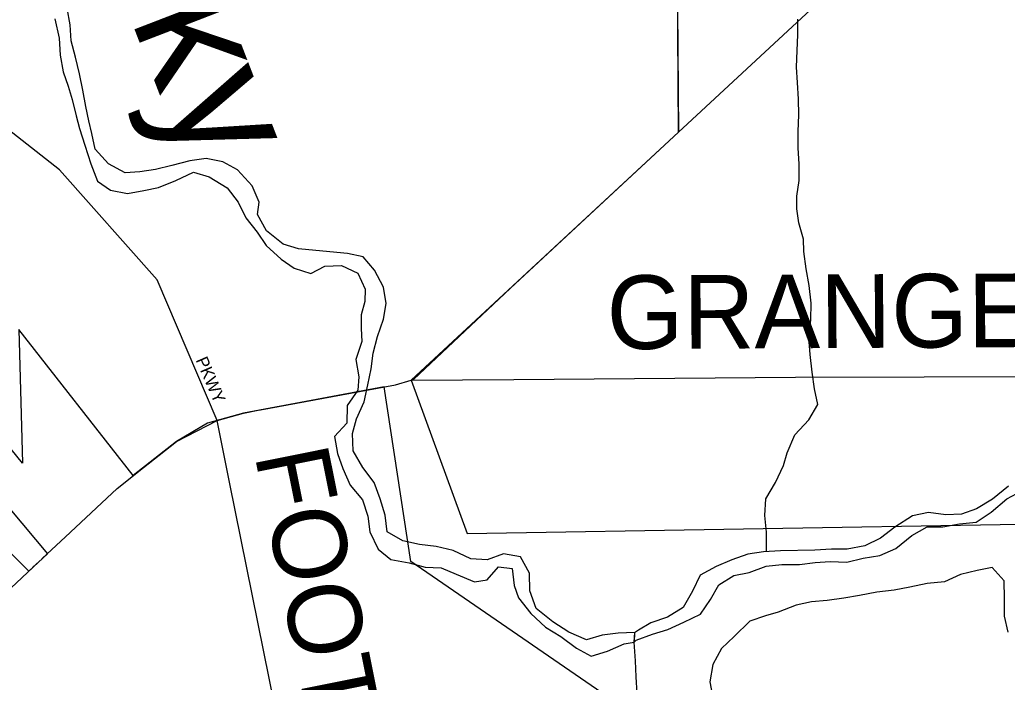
# Model space of a CAD drawing. Extents: x 1985906 to 2277390, y 930619 to 1324581.
# Drawn here: x 2150625 to 2154647, y 1147885 to 1150582 of the extents above; entities that cross this region are included whole.
import ezdxf

# ---------------------------------------------------------------- set-up
doc = ezdxf.new("R2010")
doc.units = 0
for name, color, linetype in [('GM_X_City_Street', 7, 'Continuous'), ('GM_X_City_Street_Text', 7, 'Continuous'), ('GM_X_Corporation', 7, 'Continuous'), ('GM_X_County_Road', 7, 'Continuous'), ('GM_X_County_Road_Text', 7, 'Continuous'), ('GM_X_Major_Lake', 7, 'Continuous'), ('GM_X_Major_River', 7, 'Continuous'), ('GM_X_Major_River_Text', 7, 'Continuous'), ('GM_X_Minor_River', 7, 'Continuous'), ('GM_X_State_Route', 7, 'Continuous'), ('GM_X_Township_Road', 7, 'Continuous')]:
    doc.layers.add(name, color=color, linetype=linetype)

msp = doc.modelspace()

# ---------------------------------------------------------------- linework, layer by layer
at = {"layer": 'GM_X_City_Street'}
msp.add_lwpolyline([(2151428.7, 1148950.3), (2151185, 1149523.4), (2150786.8, 1149971.6), (2150329, 1150330.1), (2149861.1, 1150479.5), (2149642.1, 1150519.4), (2146058.7, 1150549.3), (2145885.8, 1150538.1), (2145763.9, 1150518.1), (2145551.1, 1150389.9), (2145371.9, 1150240.5), (2145223.9, 1150184.4), (2145079.5, 1150167), (2144085.8, 1150150.4)], dxfattribs=at)
at = {"layer": 'GM_X_Corporation'}
for points in [[(2153303.4, 1150794.8), (2153308.8, 1150124.5), (2152624.1, 1149489.5), (2152228.9, 1149117.6), (2152218.9, 1149114.7), (2152446.7, 1148490.8), (2154698.5, 1148528.8)], [(2154691.1, 1144393.8), (2154609.5, 1144569.3), (2154568, 1144723.2), (2154424.6, 1145084.5), (2154306.7, 1145077.2), (2154279, 1145463.7), (2153339.2, 1145511.9), (2153309.4, 1147531.9), (2153191.8, 1147707), (2152218, 1148376.2), (2152108.7, 1149087.2), (2151536.3, 1148981), (2151390.1, 1148939.3), (2151263.8, 1148865.4), (2151087.4, 1148725.9), (2150621.1, 1149321.1), (2150635.4, 1148776.7), (2150590.4, 1148833.9)], [(2150479, 1148715.6), (2150737.6, 1148408.2), (2150661.9, 1148337.4), (2150257, 1148739.3)]]:
    msp.add_lwpolyline(points, dxfattribs=at)
at = {"layer": 'GM_X_County_Road'}
for points in [[(2152218.9, 1149114.7), (2152637.1, 1149118)], [(2152637.1, 1149118), (2152637.8, 1149118), (2153784.4, 1149127.4), (2154832.9, 1149129)], [(2151481, 1148692.1), (2151480.9, 1148692.3), (2151428.7, 1148950.3)], [(2152117.4, 1146221), (2152117, 1146221.4), (2152077.5, 1146256.8), (2151980.4, 1146365.9), (2151929, 1146491.6), (2151825.6, 1146989.4), (2151481, 1148692.1)]]:
    msp.add_lwpolyline(points, dxfattribs=at)
at = {"layer": 'GM_X_Major_Lake'}
msp.add_lwpolyline([(2154650.7, 1148088), (2154635.6, 1148153.8), (2154636.3, 1148226), (2154635.1, 1148298.1), (2154586.2, 1148351.3), (2154524.5, 1148340.2), (2154456.9, 1148323), (2154391.5, 1148293.8), (2154321.7, 1148286.6), (2154250.1, 1148271.3), (2154186.4, 1148260.1), (2154116.6, 1148250.9), (2154045, 1148237.6), (2153981.2, 1148226.5), (2153913.5, 1148217.3), (2153849.7, 1148212.1), (2153788, 1148199), (2153714.6, 1148169.7), (2153663, 1148154.8), (2153599.4, 1148133.6), (2153534.6, 1148070.4), (2153483.6, 1148021.4), (2153448.7, 1147956.6), (2153436, 1147886.3), (2153449.3, 1147814.4)], dxfattribs=at)
at = {"layer": 'GM_X_Major_River'}
for points in [[(2153128.1, 1148048.2), (2153130, 1148087.6), (2153062.7, 1148085), (2152996.8, 1148076.9), (2152932.8, 1148056.8), (2152860.8, 1148088.8), (2152796.8, 1148130.9), (2152728.8, 1148184.9), (2152702.7, 1148257.1), (2152700.7, 1148329.2), (2152664.6, 1148395.3), (2152594.7, 1148407.3), (2152528.7, 1148383.1), (2152462.7, 1148387.1), (2152390.7, 1148421.1), (2152320.8, 1148437.1), (2152252.8, 1148445), (2152184.8, 1148461), (2152120.8, 1148497), (2152112.7, 1148565.1), (2152092.7, 1148631.3), (2152068.6, 1148697.4), (2152022.6, 1148759.5), (2151982.6, 1148827.6), (2151980.5, 1148897.7), (2151996.4, 1148957.9), (2152028.4, 1149026), (2152042.3, 1149096.2), (2152056.2, 1149160.3), (2152064.2, 1149224.5), (2152082.1, 1149292.7), (2152106, 1149362.8), (2152118, 1149427), (2152105.9, 1149493.1), (2152069.9, 1149563.2), (2152023.9, 1149617.3), (2151959.9, 1149631.2), (2151887.9, 1149637.2), (2151760, 1149649.1), (2151698, 1149669.1), (2151629.9, 1149723.1), (2151593.9, 1149789.3), (2151599.9, 1149839.4), (2151571.8, 1149905.5), (2151511.8, 1149971.6), (2151451.8, 1150003.6), (2151383.8, 1150017.5), (2151317.8, 1150007.5), (2151243.9, 1149989.3), (2151177.9, 1149973.3), (2151114, 1149963.2), (2151054, 1149959.1), (2150986, 1149995.1), (2150932, 1150055.2), (2150917.9, 1150119.3), (2150905.9, 1150171.4), (2150893.8, 1150229.5), (2150881.8, 1150295.7), (2150867.7, 1150361.8), (2150851.7, 1150429.9), (2150833.6, 1150496), (2150829.6, 1150562.2), (2150817.5, 1150630.3)], [(2153128.1, 1148048.8), (2153130, 1148087.6), (2153062.7, 1148085), (2152996.8, 1148076.9), (2152932.8, 1148056.8), (2152860.8, 1148088.8), (2152796.8, 1148130.9), (2152728.8, 1148184.9), (2152702.7, 1148257.1), (2152700.7, 1148329.2), (2152664.6, 1148395.3), (2152594.7, 1148407.3), (2152528.7, 1148383.1), (2152462.7, 1148387.1), (2152390.7, 1148421.1), (2152320.8, 1148437.1), (2152252.8, 1148445), (2152184.8, 1148461), (2152120.8, 1148497), (2152112.7, 1148565.1), (2152092.7, 1148631.3), (2152068.6, 1148697.4), (2152022.6, 1148759.5), (2151982.6, 1148827.6), (2151980.5, 1148897.7), (2151996.4, 1148957.9), (2152028.4, 1149026), (2152042.3, 1149096.2), (2152056.2, 1149160.3), (2152064.2, 1149224.5), (2152082.1, 1149292.7), (2152106, 1149362.8), (2152118, 1149427), (2152105.9, 1149493.1), (2152069.9, 1149563.2), (2152023.9, 1149617.3), (2151959.9, 1149631.2), (2151887.9, 1149637.2), (2151760, 1149649.1), (2151698, 1149669.1), (2151629.9, 1149723.1), (2151593.9, 1149789.3), (2151599.9, 1149839.4), (2151571.8, 1149905.5), (2151511.8, 1149971.6), (2151451.8, 1150003.6), (2151383.8, 1150017.5), (2151317.8, 1150007.5), (2151243.9, 1149989.3), (2151177.9, 1149973.3), (2151114, 1149963.2), (2151054, 1149959.1), (2150986, 1149995.1), (2150932, 1150055.2), (2150917.9, 1150119.3), (2150905.9, 1150171.4), (2150893.8, 1150229.5), (2150881.8, 1150295.7), (2150867.7, 1150361.8), (2150851.7, 1150429.9), (2150833.6, 1150496), (2150829.6, 1150562.2), (2150817.5, 1150630.3)], [(2150767.6, 1150586.2), (2150785.6, 1150508), (2150789.7, 1150437.9), (2150801.7, 1150369.8), (2150821.8, 1150311.6), (2150837.8, 1150257.6), (2150853.9, 1150191.4), (2150867.9, 1150139.3), (2150890, 1150071.2), (2150914, 1149995.1), (2150942.1, 1149924.9), (2150994.1, 1149888.9), (2151064.1, 1149874.9), (2151130, 1149887), (2151190, 1149899.1), (2151259.9, 1149927.2), (2151331.9, 1149961.4), (2151395.9, 1149943.4), (2151469.9, 1149897.4), (2151513.9, 1149839.3), (2151545.9, 1149775.2), (2151592, 1149717.1), (2151628, 1149663), (2151690, 1149607), (2151742, 1149570.9), (2151810, 1149548.9), (2151868, 1149579.1), (2151935.9, 1149581.1), (2152001.9, 1149551.1), (2152032, 1149485), (2152030, 1149434.9), (2152016.1, 1149380.8), (2152016.1, 1149324.7), (2152018.2, 1149272.6), (2151994.2, 1149198.4), (2152006.3, 1149128.2), (2152002.3, 1149074.1), (2151958.4, 1149011.9)], [(2151958.4, 1149011.9), (2151956.5, 1148939.8), (2151906.5, 1148885.6), (2151918.6, 1148815.5), (2151940.6, 1148755.4), (2151970.7, 1148687.3), (2152020.7, 1148627.2), (2152042.8, 1148561.1), (2152050.8, 1148496.9), (2152084.9, 1148426.8), (2152136.9, 1148384.8), (2152210.9, 1148370.8), (2152276.8, 1148352.8), (2152340.8, 1148350.9), (2152402.8, 1148324.9), (2152476.8, 1148292.9), (2152528.8, 1148301), (2152574.7, 1148355.1), (2152630.7, 1148347.2), (2152638.7, 1148279), (2152656.8, 1148228.9), (2152706.8, 1148164.8), (2152766.8, 1148108.8), (2152828.8, 1148070.8), (2152892.9, 1148022.7), (2152952.9, 1147990.7), (2153018.8, 1148010.8), (2153086.8, 1148040.9), (2153128.1, 1148048.2)], [(2151958.4, 1149011.9), (2151956.5, 1148939.8), (2151906.5, 1148885.6), (2151918.6, 1148815.5), (2151940.6, 1148755.4), (2151970.7, 1148687.3), (2152020.7, 1148627.2), (2152042.8, 1148561.1), (2152050.8, 1148496.9), (2152084.9, 1148426.8), (2152136.9, 1148384.8), (2152210.9, 1148370.8), (2152276.8, 1148352.8), (2152340.8, 1148350.9), (2152402.8, 1148324.9), (2152476.8, 1148292.9), (2152528.8, 1148301), (2152574.7, 1148355.1), (2152630.7, 1148347.2), (2152638.7, 1148279), (2152656.8, 1148228.9), (2152706.8, 1148164.8), (2152766.8, 1148108.8), (2152828.8, 1148070.8), (2152892.9, 1148022.7), (2152952.9, 1147990.7), (2153018.8, 1148010.8), (2153086.8, 1148040.9), (2153128.1, 1148048.2)], [(2153139.6, 1147838.3), (2153136.1, 1147906.4), (2153132.6, 1147972.4), (2153127.5, 1148047.6)]]:
    msp.add_lwpolyline(points, dxfattribs=at)
at = {"layer": 'GM_X_Minor_River'}
msp.add_line((2153129, 1148086.3), (2153127.5, 1148047.6), dxfattribs=at)
for points in [[(2153666.3, 1148417.8), (2153666.9, 1148495.5), (2153659.8, 1148563.5), (2153664.5, 1148631.7), (2153703.3, 1148698.5), (2153736.1, 1148767.2), (2153751.1, 1148819.5), (2153781.8, 1148892.2), (2153838.6, 1148953.3), (2153875.5, 1149016.1), (2153862.4, 1149079.9), (2153853.2, 1149147.9), (2153843.9, 1149219.9), (2153838.7, 1149287.9), (2153847.4, 1149360.2), (2153848.2, 1149428.3), (2153841, 1149500.3), (2153827.8, 1149568.2), (2153818.6, 1149638.2), (2153817.7, 1149688.3), (2153798.5, 1149756.1), (2153789.6, 1149812), (2153790.6, 1149864.1), (2153799.5, 1149928.4), (2153800.3, 1149994.5), (2153795.2, 1150060.6), (2153796, 1150126.7), (2153798.8, 1150194.9), (2153797.7, 1150259), (2153792.5, 1150327), (2153789.4, 1150389.1), (2153792.2, 1150457.2), (2153795, 1150521.4), (2153793.9, 1150585.5)], [(2154652.3, 1148683.1), (2154587.3, 1148629.8), (2154522.1, 1148590.6), (2154460.5, 1148569.5), (2154396.7, 1148566.4), (2154326.6, 1148575.2), (2154260.9, 1148562), (2154189.8, 1148516.7), (2154130.7, 1148471.6), (2154067.4, 1148440.4), (2153995.7, 1148427.1), (2153931.8, 1148426), (2153864, 1148422.8), (2153724.2, 1148420.3), (2153654.4, 1148415.1), (2153590.6, 1148406), (2153525.1, 1148382.8), (2153461.7, 1148355.6), (2153396.4, 1148320.4), (2153365.6, 1148255.7), (2153326.8, 1148188.9), (2153263.6, 1148149.8), (2153196.1, 1148126.5), (2153145.6, 1148096.7), (2153129, 1148086.3)], [(2153127.5, 1148047.6), (2153135.4, 1148055.3), (2153202.9, 1148080.6), (2153264.5, 1148099.7), (2153329.9, 1148128.9), (2153397.2, 1148162.1), (2153438.1, 1148220.9), (2153473, 1148281.7), (2153534.2, 1148318.8), (2153595.9, 1148331.9), (2153665.4, 1148357.2), (2153729.2, 1148364.3), (2153801.1, 1148363.6), (2153864.8, 1148372.7), (2153926.7, 1148375.8), (2153994.6, 1148373), (2154060.2, 1148390.2), (2154127.9, 1148401.4), (2154193.4, 1148428.6), (2154258.4, 1148481.8), (2154321.6, 1148517), (2154385.5, 1148518.1), (2154453.2, 1148529.3), (2154521, 1148536.5), (2154582.2, 1148577.7), (2154645.2, 1148630.9), (2154706.5, 1148664)]]:
    msp.add_lwpolyline(points, dxfattribs=at)
at = {"layer": 'GM_X_State_Route'}
for points in [[(2153270.2, 1150088.7), (2153308.8, 1150124.5), (2156422.9, 1153012.1)], [(2152803, 1149655.8), (2153270.2, 1150088.7)], [(2152218.9, 1149114.7), (2152803, 1149655.8)], [(2151605.3, 1148993.8), (2152154.8, 1149095.7), (2152218.9, 1149114.7)], [(2151102.2, 1148737.6), (2151103.5, 1148738.6), (2151263.8, 1148865.4), (2151428.7, 1148950.3), (2151536.3, 1148981), (2151603.3, 1148993.4), (2151605.3, 1148993.8)], [(2150830.1, 1148494.7), (2150830.8, 1148495.4), (2151021.2, 1148673.6), (2151102.2, 1148737.6)], [(2150715.8, 1148387.8), (2150716.5, 1148388.5), (2150830.1, 1148494.7)], [(2150411.2, 1148102.8), (2150411.8, 1148103.4), (2150677.7, 1148352.2)], [(2150677.7, 1148352.2), (2150678.4, 1148352.9), (2150715.8, 1148387.8)]]:
    msp.add_lwpolyline(points, dxfattribs=at)
at = {"layer": 'GM_X_Township_Road'}
msp.add_lwpolyline([(2153308.8, 1150124.5), (2153303.8, 1150743.3), (2153303.8, 1150743.3)], dxfattribs=at)

# ---------------------------------------------------------------- texts
at = {"layer": 'GM_X_City_Street_Text'}
msp.add_text('PKWY', height=50, rotation=293.3844, dxfattribs=at).set_placement((2151340.7, 1149197))
at = {"layer": 'GM_X_County_Road_Text'}
for s, rotation, p in [('GRANGER', 0.2841, (2153016.5, 1149240.9)), ('FOOTE', 281.3557, (2151580.7, 1148811.1))]:
    msp.add_text(s, height=300, rotation=rotation, dxfattribs=at).set_placement(p)
at = {"layer": 'GM_X_Major_River_Text'}
msp.add_text('Rocky', height=500.27, rotation=291.0752, dxfattribs=at).set_placement((2150648.1, 1151695.7))

doc.saveas('drawing.dxf')
